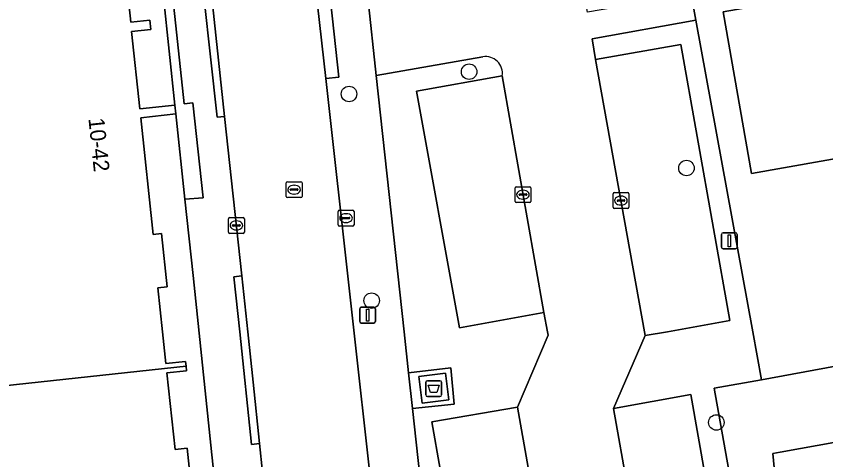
# Model space of a CAD drawing. Extents: x 161248 to 161848, y 384871 to 385383.
# Drawn here: x 161334.5 to 161385.6, y 384991.9 to 385019.9 of the extents above; entities that cross this region are included whole.
import ezdxf

# ---------------------------------------------------------------- set-up
doc = ezdxf.new("R2010")
doc.units = 0
for name, color, linetype in [('IMGEO_Afval_apart_plaats', 7, 'Continuous'), ('IMGEO_Boom', 7, 'Continuous'), ('IMGEO_Erf', 7, 'Continuous'), ('IMGEO_Groenvoorziening', 7, 'Continuous'), ('IMGEO_Haag', 7, 'Continuous'), ('IMGEO_Hek', 7, 'Continuous'), ('IMGEO_Kolk', 7, 'Continuous'), ('IMGEO_Lichtmast', 7, 'Continuous'), ('IMGEO_Pand', 7, 'Continuous'), ('IMGEO_Pand_nummerreeks', 7, 'Continuous'), ('IMGEO_Parkeervlak_open', 7, 'Continuous'), ('IMGEO_Rijbaan_lokaal_open', 7, 'Continuous'), ('IMGEO_Rioolput', 7, 'Continuous'), ('IMGEO_Voetpad_gesloten', 7, 'Continuous'), ('IMGEO_Voetpad_open', 7, 'Continuous')]:
    doc.layers.add(name, color=color, linetype=linetype)

msp = doc.modelspace()

# ---------------------------------------------------------------- linework, layer by layer
at = {"layer": 'IMGEO_Afval_apart_plaats'}
for p, q in [((161360.434, 384996.909), (161361.224, 384996.909)), ((161361.224, 384996.909), (161360.434, 384996.909)), ((161360.334, 384996.009), (161360.334, 384996.809)), ((161360.334, 384996.809), (161360.334, 384996.009)), ((161361.324, 384996.809), (161361.324, 384996.009)), ((161361.324, 384996.009), (161361.324, 384996.809)), ((161361.224, 384995.909), (161360.434, 384995.909)), ((161360.434, 384995.909), (161361.224, 384995.909))]:
    msp.add_line(p, q, dxfattribs=at)
msp.add_lwpolyline([(161360.477, 384996.623), (161361.181, 384996.623), (161361.032, 384996.153), (161360.626, 384996.153), (161360.477, 384996.623)], dxfattribs=at)
for centre, start, end in [((161360.434, 384996.809), 90, 180), ((161360.434, 384996.809), 90, 180), ((161361.224, 384996.809), 0, 90), ((161361.224, 384996.809), 360, 90), ((161360.434, 384996.009), 180, 270), ((161360.434, 384996.009), 180, 270), ((161361.224, 384996.009), 270, 0), ((161361.224, 384996.009), 270, 0)]:
    msp.add_arc(centre, 0.1, start, end, dxfattribs=at)
at = {"layer": 'IMGEO_Boom'}
for centre in [(161363.064, 385016.412), (161355.481, 385015.005), (161376.791, 385010.331), (161356.908, 385001.961), (161378.682, 384994.273)]:
    msp.add_circle(centre, 0.489, dxfattribs=at)
at = {"layer": 'IMGEO_Erf'}
for points in [[(161417, 385055.584), (161373.417, 385041.421), (161374.342, 385036.357), (161375.419, 385030.464), (161376.296, 385025.659), (161377.093, 385021.299), (161377.39, 385019.671), (161380.984, 385000), (161381.538, 384996.968), (161428.963, 385005.723), (161422.894, 385029.848), (161421.184, 385036.607), (161421.765, 385036.754)], [(161420.032, 385027.376), (161421.824, 385017.197), (161410.922, 385015.279), (161411.792, 385010.335), (161400.072, 385008.273), (161399.202, 385013.217), (161380.907, 385009.997), (161379.113, 385020.193), (161397.947, 385023.507), (161397.765, 385024.537), (161401.183, 385025.139), (161401.368, 385024.092)]]:
    msp.add_lwpolyline(points, close=True, dxfattribs=at)
at = {"layer": 'IMGEO_Groenvoorziening'}
for points in [[(161381.658, 384978.992), (161378.531, 384996.444), (161381.538, 384996.968), (161380.984, 385000), (161377.39, 385019.671), (161370.846, 385018.478), (161371.051, 385017.176), (161376.44, 385018.132), (161379.524, 385000.702), (161375.588, 385000), (161374.192, 384999.751), (161372.175, 384995.145), (161377.067, 384996.041), (161378.863, 384985.871), (161373.988, 384984.972), (161374.301, 384983.215), (161379.194, 384984.064), (161383.684, 384958.785), (161378.809, 384957.925), (161374.06, 384957.116), (161374.193, 384956.376), (161385.169, 384955.944)], [(161424.534, 385000), (161426.767, 385001.869), (161429.448, 385003.612), (161429.001, 385005.73), (161428.963, 385005.723), (161381.538, 384996.968), (161378.531, 384996.444), (161381.658, 384978.992), (161385.169, 384955.944), (161385.699, 384955.916), (161382.254, 384992.314), (161382.704, 384992.395), (161409.099, 384997.144), (161419.747, 384994.367)], [(161426.767, 385001.869), (161424.534, 385000), (161419.747, 384994.367), (161409.099, 384997.144), (161382.704, 384992.395), (161382.254, 384992.314), (161385.699, 384955.916), (161438.755, 384953.144), (161440.288, 384952.96), (161427.248, 384991.885), (161424.179, 384996.091), (161424.75, 384996.95), (161425.408, 384997.745), (161426.145, 384998.467), (161426.954, 384999.107), (161430.009, 385000.952), (161429.448, 385003.612)]]:
    msp.add_lwpolyline(points, close=True, dxfattribs=at)
for points in [[(161363.937, 385017.354), (161357.201, 385016.164), (161358.959, 385000), (161359.241, 384997.414), (161361.906, 384997.725), (161362.13, 384995.434), (161359.487, 384995.161), (161361.132, 384980.093), (161361.702, 384974.888), (161368.506, 384975.978)], [(161369.306, 384977.267), (161363.876, 384976.394), (161360.71, 384994.318), (161366.116, 384995.245), (161368.058, 384999.791), (161368.019, 385000), (161367.792, 385001.221), (161362.451, 385000.248), (161359.751, 385015.182), (161365.158, 385016.144)]]:
    msp.add_lwpolyline(points, dxfattribs=at)
msp.add_arc((161364.108, 385016.306), 1.062, 351.2465, 99.272, dxfattribs=at)
at = {"layer": 'IMGEO_Haag'}
msp.add_lwpolyline([(161381.658, 384978.992), (161378.531, 384996.444), (161381.538, 384996.968), (161380.984, 385000), (161377.39, 385019.671), (161370.846, 385018.478), (161371.051, 385017.176), (161376.44, 385018.132), (161379.524, 385000.702), (161375.588, 385000), (161374.192, 384999.751), (161372.175, 384995.145), (161377.067, 384996.041), (161378.863, 384985.871), (161373.988, 384984.972), (161374.301, 384983.215), (161379.194, 384984.064), (161383.684, 384958.785), (161378.809, 384957.925), (161374.06, 384957.116), (161374.193, 384956.376), (161385.169, 384955.944)], close=True, dxfattribs=at)
for points in [[(161363.937, 385017.354), (161357.201, 385016.164), (161358.959, 385000), (161359.241, 384997.414), (161361.906, 384997.725), (161362.13, 384995.434), (161359.487, 384995.161), (161361.132, 384980.093), (161361.702, 384974.888), (161368.506, 384975.978)], [(161369.306, 384977.267), (161363.876, 384976.394), (161360.71, 384994.318), (161366.116, 384995.245), (161368.058, 384999.791), (161368.019, 385000), (161367.792, 385001.221), (161362.451, 385000.248), (161359.751, 385015.182), (161365.158, 385016.144)]]:
    msp.add_lwpolyline(points, dxfattribs=at)
msp.add_arc((161364.108, 385016.306), 1.062, 351.2465, 99.272, dxfattribs=at)
at = {"layer": 'IMGEO_Hek'}
for points in [[(161377.39, 385019.671), (161377.093, 385021.299)], [(161381.538, 384996.968), (161380.984, 385000), (161377.39, 385019.671)]]:
    msp.add_lwpolyline(points, dxfattribs=at)
at = {"layer": 'IMGEO_Kolk'}
for p, q in [((161366.04, 385009.153), (161366.892, 385009.153)), ((161365.965, 385008.227), (161365.965, 385009.079)), ((161366.224, 385008.647), (161366.224, 385008.659)), ((161366.267, 385008.696), (161366.665, 385008.696)), ((161366.453, 385008.933), (161366.478, 385008.933)), ((161366.708, 385008.659), (161366.708, 385008.647)), ((161366.966, 385009.079), (161366.966, 385008.227)), ((161372.153, 385007.852), (161372.153, 385008.704)), ((161372.228, 385008.778), (161373.08, 385008.778)), ((161373.154, 385008.704), (161373.154, 385007.852)), ((161366.892, 385008.153), (161366.04, 385008.153)), ((161366.662, 385008.61), (161366.264, 385008.61)), ((161366.476, 385008.373), (161366.451, 385008.373)), ((161372.412, 385008.272), (161372.412, 385008.284)), ((161372.85, 385008.235), (161372.452, 385008.235)), ((161372.455, 385008.321), (161372.853, 385008.321)), ((161372.641, 385008.558), (161372.666, 385008.558)), ((161372.896, 385008.284), (161372.896, 385008.272)), ((161354.87, 385007.671), (161355.722, 385007.671)), ((161373.08, 385007.778), (161372.228, 385007.778)), ((161372.664, 385007.998), (161372.639, 385007.998)), ((161347.87, 385006.283), (161347.87, 385007.135)), ((161347.945, 385007.209), (161348.797, 385007.209)), ((161348.871, 385007.135), (161348.871, 385006.283)), ((161354.795, 385006.745), (161354.795, 385007.597)), ((161355.054, 385007.165), (161355.054, 385007.177)), ((161355.492, 385007.128), (161355.094, 385007.128)), ((161355.097, 385007.214), (161355.495, 385007.214)), ((161355.283, 385007.451), (161355.308, 385007.451)), ((161355.538, 385007.177), (161355.538, 385007.165)), ((161355.796, 385007.597), (161355.796, 385006.745)), ((161348.129, 385006.703), (161348.129, 385006.715)), ((161348.567, 385006.666), (161348.169, 385006.666)), ((161348.172, 385006.752), (161348.57, 385006.752)), ((161348.358, 385006.989), (161348.383, 385006.989)), ((161348.613, 385006.715), (161348.613, 385006.703)), ((161355.722, 385006.671), (161354.87, 385006.671)), ((161355.306, 385006.891), (161355.281, 385006.891)), ((161348.797, 385006.209), (161347.945, 385006.209)), ((161348.381, 385006.429), (161348.356, 385006.429))]:
    msp.add_line(p, q, dxfattribs=at)
for points in [[(161366.04, 385009.153), (161366.892, 385009.153)], [(161365.965, 385008.227), (161365.965, 385009.079)], [(161366.966, 385009.079), (161366.966, 385008.227)], [(161372.153, 385007.852), (161372.153, 385008.704)], [(161372.228, 385008.778), (161373.08, 385008.778)], [(161373.154, 385008.704), (161373.154, 385007.852)], [(161366.892, 385008.153), (161366.04, 385008.153)], [(161354.87, 385007.671), (161355.722, 385007.671)], [(161373.08, 385007.778), (161372.228, 385007.778)], [(161347.87, 385006.283), (161347.87, 385007.135)], [(161347.945, 385007.209), (161348.797, 385007.209)], [(161348.871, 385007.135), (161348.871, 385006.283)], [(161354.795, 385006.745), (161354.795, 385007.597)], [(161355.796, 385007.597), (161355.796, 385006.745)], [(161355.722, 385006.671), (161354.87, 385006.671)], [(161348.797, 385006.209), (161347.945, 385006.209)]]:
    msp.add_lwpolyline(points, dxfattribs=at)
for centre, radius, start, end in [((161366.042, 385009.077), 0.0765, 91.552, 178.448), ((161366.042, 385009.077), 0.0765, 91.552, 178.448), ((161366.89, 385009.077), 0.0765, 1.552, 88.448), ((161366.89, 385009.077), 0.0765, 1.552, 88.448), ((161366.264, 385008.656), 0.0403, 85.8775, 175.7526), ((161366.261, 385008.646), 0.0366, 178.938, 274.7102), ((161366.665, 385008.653), 0.043, 264.8664, 352.4533), ((161366.669, 385008.658), 0.0386, 1.7309, 96.639), ((161372.23, 385008.702), 0.0765, 91.552, 178.448), ((161372.23, 385008.702), 0.0765, 91.552, 178.448), ((161373.078, 385008.702), 0.0765, 1.552, 88.448), ((161373.078, 385008.702), 0.0765, 1.552, 88.448), ((161366.042, 385008.229), 0.0765, 181.552, 268.448), ((161366.042, 385008.229), 0.0765, 181.552, 268.448), ((161366.89, 385008.229), 0.0765, 271.552, 358.448), ((161366.89, 385008.229), 0.0765, 271.552, 358.448), ((161372.452, 385008.281), 0.0403, 85.8775, 175.7526), ((161372.449, 385008.271), 0.0366, 178.938, 274.7102), ((161372.853, 385008.278), 0.043, 264.8664, 352.4533), ((161372.857, 385008.283), 0.0386, 1.7309, 96.639), ((161354.872, 385007.595), 0.0765, 91.552, 178.448), ((161354.872, 385007.595), 0.0765, 91.552, 178.448), ((161355.72, 385007.595), 0.0765, 1.552, 88.448), ((161355.72, 385007.595), 0.0765, 1.552, 88.448), ((161372.23, 385007.854), 0.0765, 181.552, 268.448), ((161372.23, 385007.854), 0.0765, 181.552, 268.448), ((161373.078, 385007.854), 0.0765, 271.552, 358.448), ((161373.078, 385007.854), 0.0765, 271.552, 358.448), ((161347.947, 385007.133), 0.0765, 91.552, 178.448), ((161347.947, 385007.133), 0.0765, 91.552, 178.448), ((161348.795, 385007.133), 0.0765, 1.552, 88.448), ((161348.795, 385007.133), 0.0765, 1.552, 88.448), ((161355.094, 385007.174), 0.0403, 85.8775, 175.7526), ((161355.091, 385007.164), 0.0366, 178.938, 274.7102), ((161355.495, 385007.171), 0.043, 264.8664, 352.4533), ((161355.499, 385007.176), 0.0386, 1.7309, 96.639), ((161348.169, 385006.712), 0.0403, 85.8775, 175.7526), ((161348.166, 385006.702), 0.0366, 178.938, 274.7102), ((161348.57, 385006.709), 0.043, 264.8664, 352.4533), ((161348.574, 385006.714), 0.0386, 1.7309, 96.639), ((161354.872, 385006.747), 0.0765, 181.552, 268.448), ((161354.872, 385006.747), 0.0765, 181.552, 268.448), ((161355.72, 385006.747), 0.0765, 271.552, 358.448), ((161355.72, 385006.747), 0.0765, 271.552, 358.448), ((161347.947, 385006.285), 0.0765, 181.552, 268.448), ((161347.947, 385006.285), 0.0765, 181.552, 268.448), ((161348.795, 385006.285), 0.0765, 271.552, 358.448), ((161348.795, 385006.285), 0.0765, 271.552, 358.448)]:
    msp.add_arc(centre, radius, start, end, dxfattribs=at)
for centre, major_axis, ratio, start_param, end_param in [((161366.452, 385008.653), (-0.387, 0.002), 0.722429, 4.712389, 7.853982), ((161366.477, 385008.653), (-0.39, 0.002), 0.717154, 1.570796, 4.712389), ((161372.64, 385008.278), (-0.387, 0.002), 0.722429, 4.712389, 7.853982), ((161372.665, 385008.278), (-0.39, 0.002), 0.717154, 1.570796, 4.712389), ((161355.282, 385007.171), (-0.387, 0.002), 0.722429, 4.712389, 7.853982), ((161355.307, 385007.171), (-0.39, 0.002), 0.717154, 1.570796, 4.712389), ((161348.357, 385006.709), (-0.387, 0.002), 0.722429, 4.712389, 7.853982), ((161348.382, 385006.709), (-0.39, 0.002), 0.717154, 1.570796, 4.712389)]:
    msp.add_ellipse(centre, major_axis=major_axis, ratio=ratio, start_param=start_param, end_param=end_param, dxfattribs=at)
at = {"layer": 'IMGEO_Lichtmast'}
for p, q in [((161379.006, 385005.34), (161379.006, 385006.14)), ((161379.006, 385006.14), (161379.006, 385005.34)), ((161379.106, 385006.24), (161379.896, 385006.24)), ((161379.896, 385006.24), (161379.106, 385006.24)), ((161379.996, 385006.14), (161379.996, 385005.34)), ((161379.996, 385005.34), (161379.996, 385006.14)), ((161379.896, 385005.24), (161379.106, 385005.24)), ((161379.106, 385005.24), (161379.896, 385005.24)), ((161356.255, 385001.547), (161357.045, 385001.547)), ((161357.045, 385001.547), (161356.255, 385001.547)), ((161356.155, 385000.647), (161356.155, 385001.447)), ((161356.155, 385001.447), (161356.155, 385000.647)), ((161357.145, 385001.447), (161357.145, 385000.647)), ((161357.145, 385000.647), (161357.145, 385001.447)), ((161357.045, 385000.547), (161356.255, 385000.547)), ((161356.255, 385000.547), (161357.045, 385000.547))]:
    msp.add_line(p, q, dxfattribs=at)
for points in [[(161379.426, 385006.115), (161379.576, 385006.115), (161379.576, 385005.365), (161379.426, 385005.365), (161379.426, 385006.115)], [(161356.575, 385001.422), (161356.725, 385001.422), (161356.725, 385000.672), (161356.575, 385000.672), (161356.575, 385001.422)]]:
    msp.add_lwpolyline(points, dxfattribs=at)
for centre, start, end in [((161379.106, 385006.14), 90, 180), ((161379.106, 385006.14), 90, 180), ((161379.896, 385006.14), 0, 90), ((161379.896, 385006.14), 360, 90), ((161379.106, 385005.34), 180, 270), ((161379.106, 385005.34), 180, 270), ((161379.896, 385005.34), 270, 0), ((161379.896, 385005.34), 270, 0), ((161356.255, 385001.447), 90, 180), ((161356.255, 385001.447), 90, 180), ((161357.045, 385001.447), 0, 90), ((161357.045, 385001.447), 360, 90), ((161356.255, 385000.647), 180, 270), ((161356.255, 385000.647), 180, 270), ((161357.045, 385000.647), 270, 0), ((161357.045, 385000.647), 270, 0)]:
    msp.add_arc(centre, 0.1, start, end, dxfattribs=at)
at = {"layer": 'IMGEO_Pand'}
for points in [[(161411.792, 385010.335), (161410.922, 385015.279), (161421.824, 385017.197), (161420.032, 385027.376), (161401.368, 385024.092), (161401.183, 385025.139), (161397.765, 385024.537), (161397.947, 385023.507), (161379.113, 385020.193), (161380.907, 385009.997), (161399.202, 385013.217), (161400.072, 385008.273)], [(161345.156, 384998.117), (161343.922, 384997.985), (161343.705, 385000), (161343.407, 385002.773), (161343.994, 385002.836), (161343.632, 385006.194), (161343.119, 385006.139), (161342.326, 385013.505), (161344.547, 385013.744), (161344.487, 385014.308), (161342.278, 385014.07), (161341.754, 385018.946), (161342.964, 385019.076), (161342.901, 385019.664), (161341.712, 385019.536), (161341.199, 385024.305), (161343.408, 385024.542), (161343.36, 385024.989), (161335.88, 385024.185), (161326.879, 385023.217), (161329.376, 385000), (161329.788, 384996.166), (161345.188, 384997.822)], [(161345.639, 384981.819), (161344.847, 384989.184), (161345.626, 384989.268), (161345.261, 384992.657), (161344.504, 384992.575), (161343.986, 384997.395), (161345.22, 384997.527), (161345.188, 384997.822), (161329.788, 384996.166), (161332.09, 384974.761), (161347.464, 384976.414), (161347.432, 384976.709), (161346.267, 384976.583), (161345.763, 384981.275), (161347.976, 384981.513), (161347.916, 384982.064)]]:
    msp.add_lwpolyline(points, close=True, dxfattribs=at)
at = {"layer": 'IMGEO_Parkeervlak_open'}
for points in [[(161371.051, 385017.176), (161374.147, 385000), (161374.192, 384999.751), (161375.588, 385000), (161379.524, 385000.702), (161376.44, 385018.132)], [(161359.751, 385015.182), (161362.451, 385000.248), (161367.792, 385001.221), (161365.158, 385016.144)], [(161372.175, 384995.145), (161373.988, 384984.972), (161378.863, 384985.871), (161377.067, 384996.041)], [(161360.71, 384994.318), (161363.876, 384976.394), (161369.306, 384977.267), (161366.116, 384995.245)]]:
    msp.add_lwpolyline(points, close=True, dxfattribs=at)
at = {"layer": 'IMGEO_Rijbaan_lokaal_open'}
for points in [[(161426.573, 384952.665), (161402.419, 384953.798), (161366.213, 384955.463), (161364.762, 384955.736), (161364.406, 384955.834), (161363.914, 384956.01), (161363.438, 384956.23), (161362.985, 384956.491), (161362.556, 384956.792), (161362.157, 384957.13), (161361.789, 384957.502), (161361.455, 384957.906), (161361.159, 384958.338), (161360.903, 384958.794), (161360.689, 384959.272), (161360.518, 384959.767), (161360.392, 384960.275), (161360.312, 384960.792), (161359.166, 384970.229), (161358.591, 384974.963), (161354.008, 385015.984), (161353.49, 385020.627), (161352.463, 385029.816), (161352.337, 385032.267)], [(161370.536, 384970.353), (161372.349, 384960.161), (161373.016, 384956.422), (161374.193, 384956.376), (161374.06, 384957.116), (161378.809, 384957.925), (161374.301, 384983.215), (161373.988, 384984.972), (161372.175, 384995.145), (161374.192, 384999.751), (161374.147, 385000), (161371.051, 385017.176), (161370.846, 385018.478), (161377.39, 385019.671), (161377.093, 385021.299), (161370.537, 385020.16), (161369.079, 385028.35)], [(161346.251, 385026.361), (161346.412, 385024.863), (161347.622, 385013.594), (161348.704, 385003.522), (161349.082, 385000), (161349.418, 384996.821), (161349.825, 384992.946), (161350.964, 384982.082), (161352.083, 384971.42), (161352.903, 384963.923), (161353.293, 384960.634), (161353.412, 384959.629), (161353.581, 384958.529), (161353.847, 384957.448), (161354.209, 384956.395), (161354.511, 384955.694), (161355.059, 384954.63), (161355.7, 384953.619), (161356.682, 384952.243)], [(161363.051, 385022.242), (161356.664, 385021.107), (161357.201, 385016.164), (161363.937, 385017.354)], [(161365.158, 385016.144), (161367.792, 385001.221), (161368.019, 385000), (161368.058, 384999.791), (161366.116, 384995.245), (161369.306, 384977.267)]]:
    msp.add_lwpolyline(points, dxfattribs=at)
msp.add_arc((161364.108, 385016.306), 1.062, 351.2465, 99.272, dxfattribs=at)
at = {"layer": 'IMGEO_Rioolput'}
for p, q in [((161351.515, 385008.542), (161351.515, 385009.394)), ((161351.59, 385009.468), (161352.442, 385009.468)), ((161352.003, 385009.248), (161352.028, 385009.248)), ((161352.516, 385009.394), (161352.516, 385008.542)), ((161351.774, 385008.962), (161351.774, 385008.974)), ((161352.212, 385008.925), (161351.814, 385008.925)), ((161351.817, 385009.011), (161352.215, 385009.011)), ((161352.026, 385008.688), (161352.001, 385008.688)), ((161352.258, 385008.974), (161352.258, 385008.962)), ((161352.442, 385008.468), (161351.59, 385008.468))]:
    msp.add_line(p, q, dxfattribs=at)
for points in [[(161351.515, 385008.542), (161351.515, 385009.394)], [(161351.59, 385009.468), (161352.442, 385009.468)], [(161352.516, 385009.394), (161352.516, 385008.542)], [(161352.442, 385008.468), (161351.59, 385008.468)]]:
    msp.add_lwpolyline(points, dxfattribs=at)
for centre, radius, start, end in [((161351.592, 385009.392), 0.0765, 91.552, 178.448), ((161351.592, 385009.392), 0.0765, 91.552, 178.448), ((161352.44, 385009.392), 0.0765, 1.552, 88.448), ((161352.44, 385009.392), 0.0765, 1.552, 88.448), ((161351.814, 385008.971), 0.0403, 85.8775, 175.7526), ((161351.811, 385008.961), 0.0366, 178.938, 274.7102), ((161352.215, 385008.968), 0.043, 264.8664, 352.4533), ((161352.219, 385008.973), 0.0386, 1.7309, 96.639), ((161351.592, 385008.544), 0.0765, 181.552, 268.448), ((161351.592, 385008.544), 0.0765, 181.552, 268.448), ((161352.44, 385008.544), 0.0765, 271.552, 358.448), ((161352.44, 385008.544), 0.0765, 271.552, 358.448)]:
    msp.add_arc(centre, radius, start, end, dxfattribs=at)
for centre, major_axis, ratio, start_param, end_param in [((161352.002, 385008.968), (-0.387, 0.002), 0.722429, 4.712389, 7.853982), ((161352.027, 385008.968), (-0.39, 0.002), 0.717154, 1.570796, 4.712389)]:
    msp.add_ellipse(centre, major_axis=major_axis, ratio=ratio, start_param=start_param, end_param=end_param, dxfattribs=at)
at = {"layer": 'IMGEO_Voetpad_gesloten'}
msp.add_lwpolyline([(161361.582, 384997.384), (161359.89, 384997.171), (161360.102, 384995.489), (161361.794, 384995.702)], close=True, dxfattribs=at)
at = {"layer": 'IMGEO_Voetpad_open'}
for points in [[(161361.132, 384980.093), (161359.487, 384995.161), (161359.241, 384997.414), (161358.959, 385000), (161357.201, 385016.164), (161356.664, 385021.107), (161355.452, 385032.254), (161355.445, 385032.397), (161355.448, 385032.771), (161355.485, 385033.144), (161355.555, 385033.511), (161355.658, 385033.871), (161355.793, 385034.22), (161355.958, 385034.556), (161356.152, 385034.875), (161356.374, 385035.176), (161356.623, 385035.456), (161356.895, 385035.713), (161357.189, 385035.944), (161357.503, 385036.149), (161357.833, 385036.324), (161358.178, 385036.469), (161357.402, 385039.915)], [(161352.337, 385032.267), (161352.463, 385029.816), (161353.49, 385020.627), (161354.33, 385020.717), (161354.832, 385016.072), (161354.008, 385015.984), (161358.591, 384974.963)], [(161343.203, 385026.481), (161343.3, 385025.559), (161343.862, 385025.619), (161345.069, 385014.386), (161345.626, 385014.446), (161346.272, 385008.441), (161345.12, 385008.375), (161345.635, 385003.548), (161346.825, 384992.221), (161347.327, 384987.554), (161347.916, 384982.064), (161347.976, 384981.513), (161349.099, 384971.364), (161349.162, 384970.781), (161351.394, 384949.836), (161352.34, 384941.034), (161352.588, 384941.054), (161354.608, 384941.218)], [(161352.083, 384971.42), (161351.587, 384971.365), (161350.468, 384982.027), (161350.964, 384982.082), (161349.825, 384992.946), (161349.328, 384992.891), (161348.579, 385000), (161348.214, 385003.468), (161348.704, 385003.522), (161347.622, 385013.594), (161347.145, 385013.539), (161345.918, 385024.806), (161346.412, 385024.863), (161346.251, 385026.361)]]:
    msp.add_lwpolyline(points, dxfattribs=at)
for points in [[(161345.12, 385008.375), (161346.272, 385008.441), (161345.626, 385014.446), (161345.069, 385014.386), (161343.862, 385025.619), (161343.3, 385025.559), (161343.36, 385024.989), (161343.408, 385024.542), (161344.487, 385014.308), (161344.547, 385013.744)], [(161343.408, 385024.542), (161341.199, 385024.305), (161341.712, 385019.536), (161342.901, 385019.664), (161342.964, 385019.076), (161341.754, 385018.946), (161342.278, 385014.07), (161344.487, 385014.308)], [(161346.412, 385024.863), (161345.918, 385024.806), (161347.145, 385013.539), (161347.622, 385013.594)], [(161354.33, 385020.717), (161353.49, 385020.627), (161354.008, 385015.984), (161354.832, 385016.072)], [(161346.825, 384992.221), (161345.635, 385003.548), (161345.12, 385008.375), (161344.547, 385013.744), (161342.326, 385013.505), (161343.119, 385006.139), (161343.632, 385006.194), (161343.994, 385002.836), (161343.407, 385002.773), (161343.705, 385000), (161343.922, 384997.985), (161345.156, 384998.117), (161345.188, 384997.822), (161345.22, 384997.527), (161343.986, 384997.395), (161344.504, 384992.575), (161345.261, 384992.657), (161345.626, 384989.268), (161344.847, 384989.184), (161345.639, 384981.819), (161347.916, 384982.064), (161347.327, 384987.554)], [(161349.825, 384992.946), (161349.418, 384996.821), (161349.082, 385000), (161348.704, 385003.522), (161348.214, 385003.468), (161348.579, 385000), (161349.328, 384992.891)], [(161359.487, 384995.161), (161362.13, 384995.434), (161361.906, 384997.725), (161359.241, 384997.414)], [(161360.102, 384995.489), (161359.89, 384997.171), (161361.582, 384997.384), (161361.794, 384995.702)]]:
    msp.add_lwpolyline(points, close=True, dxfattribs=at)

# ---------------------------------------------------------------- texts
at = {"layer": 'IMGEO_Pand_nummerreeks'}
msp.add_text('10-42', height=1, rotation=275.9067, dxfattribs=at).set_placement((161339.024, 385013.454))

doc.saveas('drawing.dxf')
